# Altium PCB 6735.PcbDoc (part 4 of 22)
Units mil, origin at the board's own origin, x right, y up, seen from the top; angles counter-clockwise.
Board outline 2641.73 x 5165.35 mil, 6 copper layers (Top, Inner Layer 2, Inner Layer 3, Inner Layer 4, Inner Layer 5, Bottom), stack 35.7 mil thick; 1011 components, 790 nets, 4118 pads, 9325 vias.
Unrouted connection lines stored in the file: 4610.
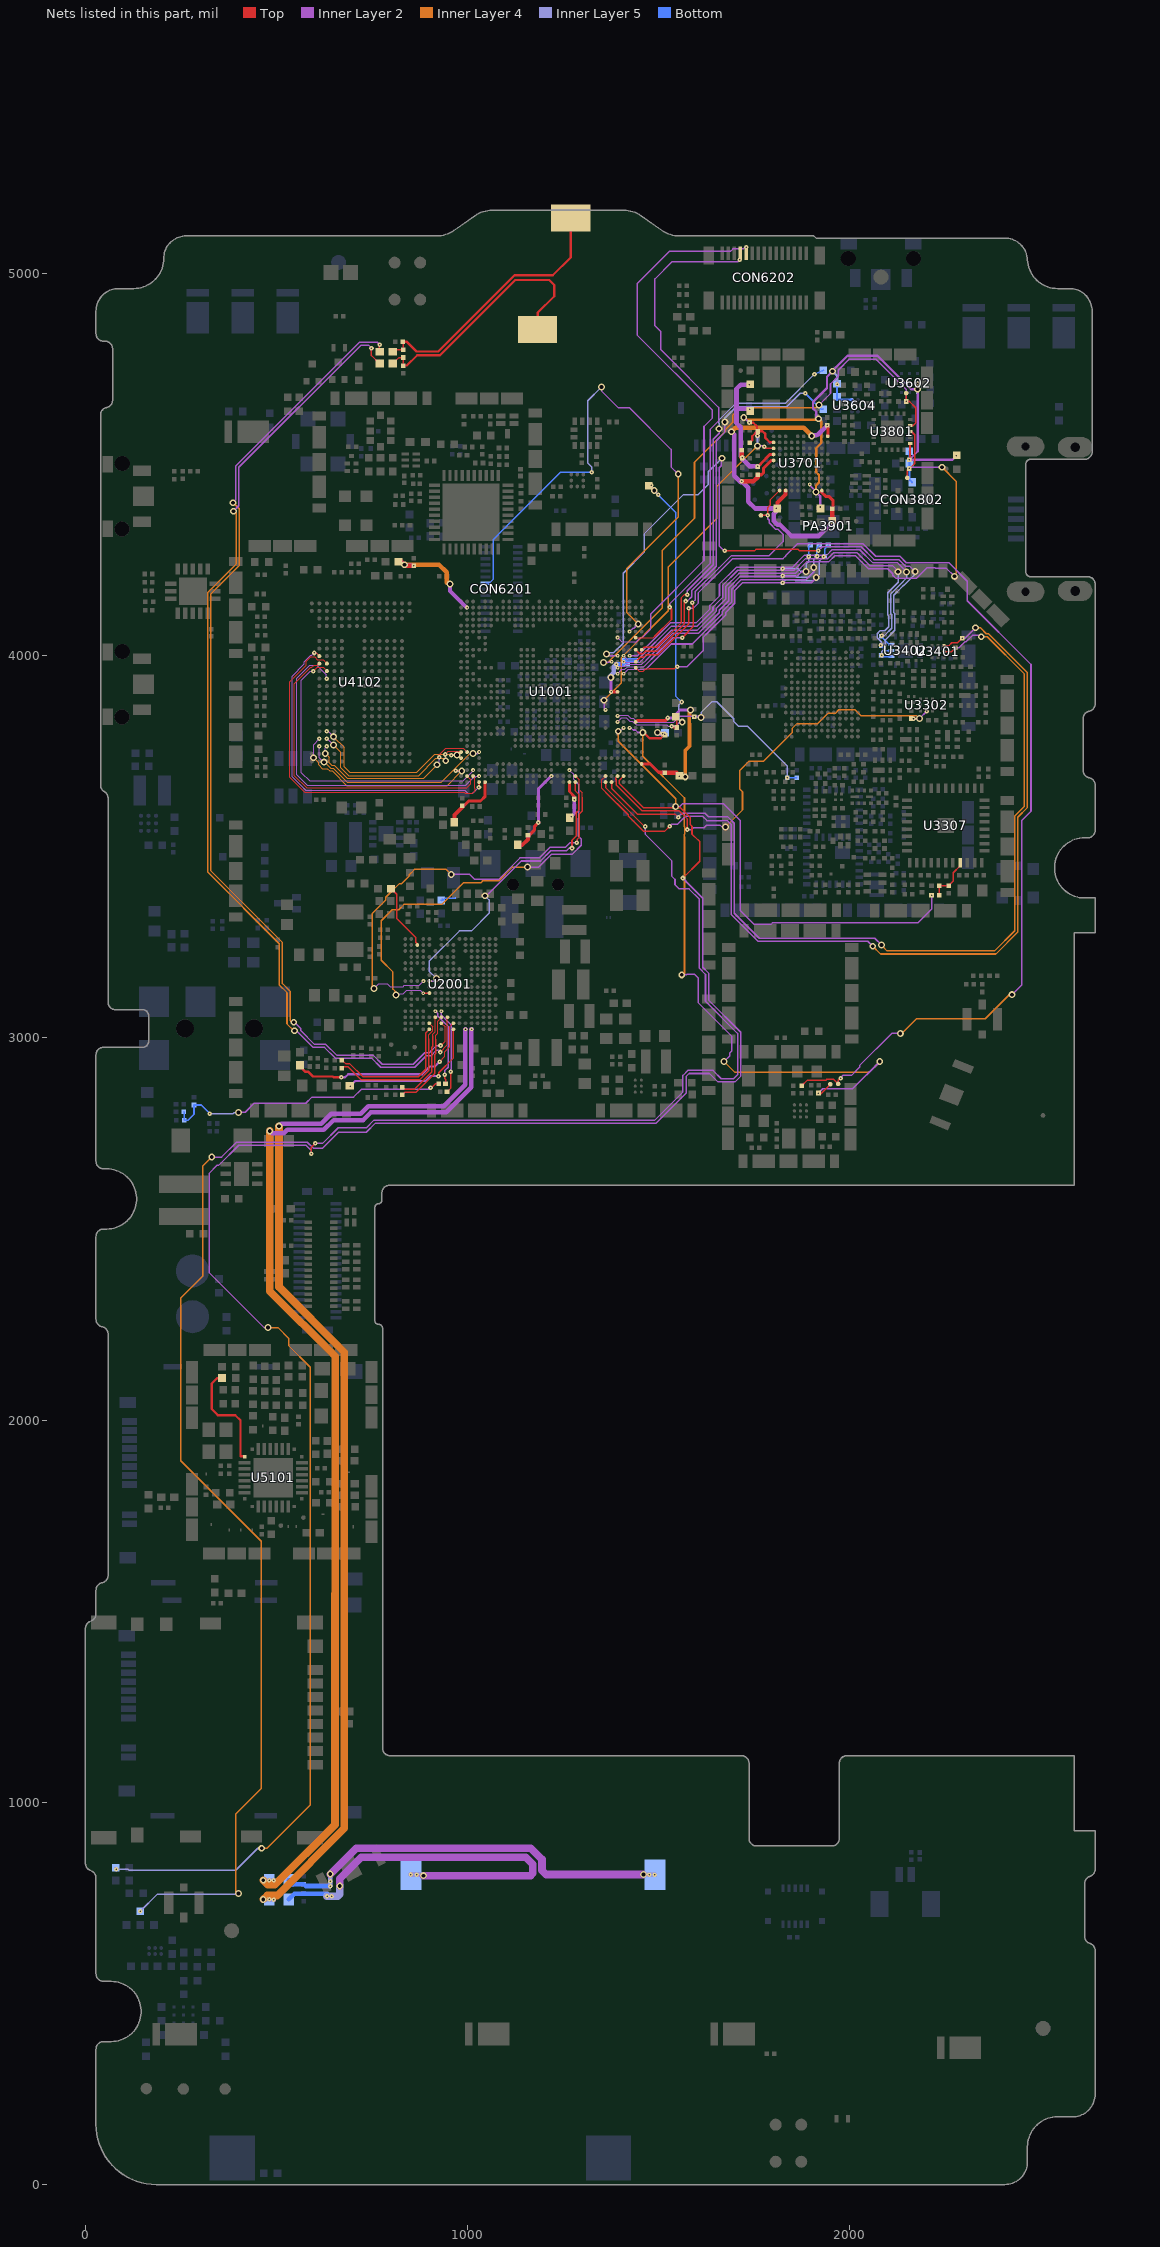
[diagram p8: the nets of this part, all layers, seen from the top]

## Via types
v1: diameter 12, hole 4, Top to Inner Layer 2, 3329 vias
v2: diameter 12, hole 4, Inner Layer 5 to Bottom, 3071 vias
v3: diameter 18, hole 10, Inner Layer 2 to Inner Layer 5, 1928 vias
v4: diameter 10, hole 4, Top to Inner Layer 2, 525 vias
v5: diameter 20, hole 12, Top to Bottom, 472 vias

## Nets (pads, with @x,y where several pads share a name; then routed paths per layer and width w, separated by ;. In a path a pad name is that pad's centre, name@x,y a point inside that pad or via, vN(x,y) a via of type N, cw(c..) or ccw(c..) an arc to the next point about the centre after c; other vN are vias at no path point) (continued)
ANT_P: C5101.2 U5101.25 | length 292.5
  Top w6: C5101.2@357.31,2110.09 357.31,2109.45 344.31,2109.45 330.41,2095.55 330.41,2029.09 346.49,2013.02 391.79,2013.02 405.38,1999.43 405.38,1905.54 415.07,1905.54 U5101.25@416.4,1904.21
APC1: R3301.1 U1001.AH10 | length 1282.5
  Top w4: R3301.1@2213.65,3373.59 v1(2213.8,3373.48)
  Inner Layer 2 w4: v3(1393.95,3802.49) 1391.03,3799.43 1393.69,3796.76 v4(1407.93,3811) ; v3(1544.25,3605.09) 1554.21,3605.09 1561.21,3612.09 1669.9,3612.09 1713.65,3568.34 1713.65,3332.62 1749.5,3296.77 1793.56,3296.77 1797.87,3301.08 2178.25,3301.08 2213.8,3336.62 v1(2213.8,3373.48)
  Inner Layer 4 w4: v3(1393.95,3802.49) 1393.95,3776.3 1544.25,3626 v3(1544.25,3605.09)
APC1_TXM: C3304.1 R3301.2 R3302.1 U3307.8 | length 121.9
  Top w4: R3301.2@2233.65,3373.59 R3302.1@2233.65,3398.59 C3304.1@2258.65,3398.59 2270.65,3410.59 2270.65,3432.09 2288.45,3449.88 U3307.8@2288.45,3458.15
APC2: R3908.1 TP3905.1 U1001.AJ10 | length 1706.8
  Top w4: R3908.1@1917.95,2855.96 v1(1916.95,2854.96) 1918.33,2853.58 1923.57,2853.58 TP3905.1@1948.95,2878.96
  Inner Layer 2 w4: v4(1423.68,3811) 1427.65,3811 1433.06,3805.59 1438.8,3805.59 1445.3,3799.09 v3(1458.3,3799.09) ; v3(1560.2,3165.08) 1572.09,3165.08 1573.92,3166.91 1592.74,3166.91 1603.6,3156.05 1603.6,3091.67 1690.31,3004.96 1690.31,2965.24 1685.42,2960.35 1685.42,2953.02 v3(1670.78,2938.38) ; v1(1916.95,2854.96) 1928.95,2866.96 2007.14,2866.96 v3(2078.04,2937.87)
  Inner Layer 4 w4: v3(1458.3,3799.09) 1458.3,3736.84 1567.31,3627.83 1567.31,3593.32 1567.15,3593.16 1567.15,3552.74 1567.56,3552.33 1567.56,3533.28 1567.15,3532.87 1567.15,3526.61 1567.31,3526.45 1567.31,3168.09 1566.13,3166.91 1560.31,3166.91 1560.1,3165.09 v3(1560.2,3165.08) ; v3(1670.78,2938.38) 1699.61,2909.56 2049.74,2909.56 v3(2078.04,2937.87)
AU_HPL: R6003.1 U2001.H15 | length 514.3
  Top w3: v1(926.9,2938.09) 940.18,2951.37 940.18,2964.03 953.31,2977.16 953.31,3028.96 U2001.H15@962.83,3038.47
  Top w4: U2001.H15@963.28,3038.47 U2001.H15@962.95,3038.47 ; U2001.H15@962.83,3038.47 963.05,3038.69 962.82,3038.92 U2001.H15@962.83,3038.47 ; U2001.H15@962.83,3038.47 962.95,3038.34 U2001.H15@962.95,3038.47 ; U2001.H15@962.83,3038.47 U2001.H15@962.95,3038.47 ; U2001.H15@962.83,3038.47 U2001.H15@962.95,3038.47
  Top w6: R6003.1@561.31,2928.09 561.31,2925.68 575.9,2911.09 583.38,2911.09 595.38,2899.09 646.55,2899.09 648.76,2896.88 v1(669.13,2896.88)
  Inner Layer 2 w6: v1(669.13,2896.88) 679.1,2896.88 687.31,2905.09 880.94,2905.09 900.94,2925.09 913.9,2925.09 v1(926.9,2938.09)
AU_HPR: R6004.1 U2001.H16 | length 389.4
  Top w4: R6004.1@690.95,2874.83 691.95,2874.83 692.49,2874.3 v1(692.49,2873.47) ; v1(923.63,2900.12) 923.93,2898.74 924.31,2898.74 924.31,2909.09 962.83,2947.6 U2001.H16@962.83,3022.72 ; U2001.H16@962.83,3022.72 963.02,3022.72 U2001.H16@962.83,3022.72
  Top w6: U2001.H16@961.95,3021.85 U2001.H16@962.83,3022.72 U2001.H16@961.95,3021.85
  Inner Layer 2 w6: v1(692.49,2873.47) 706.1,2887.09 890.84,2887.09 903.87,2900.12 v1(923.63,2900.12)
AU_HSN: R6021.1 U2001.J14 | length 2692.8
  Top w3: v1(928.31,2963.09) 946.75,2981.53 946.75,3054.22 U2001.J14@947.08,3054.22
  Top w4: v1(748.31,4804.09) 748.31,4785.13 768.95,4764.49 R6021.1@768.95,4765.49 ; R6021.1@768.95,4772.49 R6021.1@768.95,4765.49 ; R6021.1@769.35,4765.89 R6021.1@768.95,4765.49 ; R6021.1@769.95,4764.49 R6021.1@768.95,4765.49
  Inner Layer 2 w4: v3(387.31,4378.09) 401.31,4392.09 401.31,4493.18 719.96,4811.83 741.57,4811.83 748.31,4805.09 v1(748.31,4804.09) ; v3(546.95,3018.83) 552.31,3018.83 596.05,2975.09 625.61,2975.09 653.61,2947.09 748.29,2947.09 772.29,2923.09 861.53,2923.09 891.53,2953.09 903.75,2953.09 918.75,2968.09 923.31,2968.09 926.97,2964.43 v1(928.31,2963.09)
  Inner Layer 4 w4: v3(387.31,4378.09) 390.31,4378.09 394.31,4374.09 394.31,4240.08 320.31,4166.08 320.31,3433.61 507.31,3246.61 507.31,3138.71 527.31,3118.71 527.31,3036.75 546.09,3017.97 v3(546.95,3018.83)
AU_HSP: R6022.1 U2001.K15 | length 2646.6
  Top w3: v1(928.98,2980.09) 929.32,2980.09 940.75,2991.52 940.75,3029.05 U2001.K15@931.33,3038.47
  Top w4: R6022.1@769.35,4795.89 R6022.1@768.95,4795.49 ; v1(769.48,4813.59) 768.95,4813.06 R6022.1@768.95,4795.49 ; R6022.1@769.95,4795.49 767.95,4794.49 R6022.1@768.95,4795.49 ; U2001.K15@930.98,3038.82 U2001.K15@931.33,3038.47 ; U2001.K15@930.98,3038.82 931.33,3038.65 U2001.K15@931.33,3038.47 ; U2001.K15@930.98,3038.82 U2001.K15@931.33,3038.47
  Inner Layer 2 w4: v3(386.31,4400.09) 393.31,4407.09 393.31,4496.5 410.9,4514.09 594.52,4697.7 716.65,4819.83 763.24,4819.83 v1(769.48,4813.59) ; v3(544.95,3040.83) 545.99,3041.87 563.84,3024.02 563.84,3018.62 599.37,2983.09 628.93,2983.09 656.93,2955.09 752.66,2955.09 776.66,2931.09 857.85,2931.09 887.85,2961.09 899.3,2961.09 918.3,2980.09 v1(928.98,2980.09)
  Inner Layer 4 w4: v3(386.31,4400.09) 386.53,4400.31 402.31,4384.53 402.31,4235.95 328.31,4161.95 328.31,3436.93 515.31,3249.93 515.31,3142.05 535.31,3122.05 535.31,3046.09 540.57,3040.83 v3(544.95,3040.83)
AU_OUT0_N_OUT: C6025.2 C6032.1 R6021.2 REC6001.2 | length 682.6
  Top w4: R6021.2@803.95,4764.49 804.95,4764.49 820.55,4780.09 C6025.2@831.31,4780.09 C6032.1@831.31,4759.09
  Top w6: C6032.1@831.31,4759.09 840.91,4759.09 867.91,4786.09 927.31,4786.09 1124.31,4983.09 1213.31,4983.09 1226.31,4970.09 1226.31,4940.63 1182.99,4897.31 REC6001.2@1183,4853.42
AU_OUT0_P_OUT: C6025.1 C6031.1 R6022.2 REC6001.1 | length 705
  Top w4: R6022.2@803.95,4795.49 804.95,4795.49 809.55,4800.09 C6025.1@831.31,4800.09 831.46,4800.24 831.46,4819.94 831.31,4820.09 C6031.1@830.31,4821.09
  Top w6: C6031.1@830.31,4821.09 841.2,4821.09 866.2,4796.09 923.17,4796.09 1122.4,4995.32 1222.75,4995.32 1269.61,5042.18 REC6001.1@1269.61,5144.76
AU_SPK1N: R6019.2 U2001.E16 | length 2918.5
  Inner Layer 2 w12: v3(482.31,2756.35) 488.57,2750.09 518.47,2750.09 527.91,2759.53 623.8,2759.53 649.37,2785.09 726.94,2785.09 746.94,2805.09 943.75,2805.09 984.75,2846.09 984.86,2846.09 1009.52,2870.75 1009.52,3022.17 v4(1010.07,3022.72)
  Inner Layer 4 w20: v3(465.31,796.09) 477.31,784.09 495.37,784.09 652.95,941.67 652.95,1545.47 653.31,1545.83 653.31,2166.76 482.31,2337.76 v3(482.31,2756.35)
  Inner Layer 5 w12: v3(465.31,796.09) v2@478.67,796.09 ; v2(480.82,795.85) v2@478.67,796.08 ; v2(492.95,795.78) 492.64,796.09 v2@478.67,796.09
  Bottom w4: v2(480.82,795.85) R6019.2@480.72,796.09 490.31,796.09 491.31,795.09 491.36,795.11 v2(492.95,795.78)
AU_SPK1P: R6020.2 U2001.F16 | length 2926.3
  Inner Layer 2 w12: v3(506.31,2769.09) 512.78,2775.56 617.16,2775.56 642.7,2801.09 719.86,2801.09 739.86,2821.09 937.12,2821.09 978.12,2862.09 978.23,2862.09 993.42,2877.28 993.42,3021.81 v4(994.32,3022.72)
  Inner Layer 4 w20: v3(465.31,746.09) 475.31,756.09 501.31,756.09 676.95,931.73 676.95,1524.17 677.31,1524.54 677.31,2177.42 506.31,2348.42 v3(506.31,2769.09)
  Inner Layer 5 w12: v3(465.31,746.09) v2(480.72,746.09) 480.72,745.87 492.97,745.87 v2(492.97,745.65)
  Bottom w4: v2(492.97,745.65) 491.31,746.09 v2(480.72,746.09) ; v2(480.72,746.09) 476.72,750.09 v2(480.72,746.09)
AU_SPK_N: C6024.1 R6019.1 SPK6001.1 | length 1125.5
  Inner Layer 2 w20: v3(640.31,812.09) 708.31,880.09 1165.31,880.09 1194.31,851.09 1194.31,822.09 1205.31,811.09 v3(1459.65,811.09)
  Inner Layer 5 w4: v2(1475.21,810.82) 1475.21,810.71 v2@1489.85,810.71
  Inner Layer 5 w12: v2(639.96,780.86) 640.14,780.86 640.14,812.09 v3(640.31,812.09) ; v3(1459.65,811.09) 1459.65,810.84 1489.85,810.84 1489.85,810.71 v2(1489.85,810.59)
  Bottom w4: v2(639.96,780.86) 639.73,781.09 637.3,783.52 639.59,785.81 638.31,787.09 639.96,787.09 640.31,787.09 640.56,790.95 639.96,791.1 639.58,791.19 639.96,792.75 v2(640.22,793.82) ; SPK6001.1@1489.85,810.59 1489.85,815.55 v2(1489.85,810.59)
  Bottom w12: R6019.1@531.9,796.09 541.91,786.09 C6024.1@571.31,786.09 576.31,781.09 v2@639.73,781.09 ; v2(639.96,780.86) 639.96,787.09 639.96,791.1 639.96,792.75 639.96,793.56 v2(640.22,793.82)
AU_SPK_P: C6023.2 R6020.1 SPK6001.2 | length 1134.1
  Inner Layer 2 w20: v3(665.31,781.09) 665.31,800.09 721.31,856.09 1152.31,856.09 1170.31,838.09 1170.31,814.09 1164.31,808.09 v3(884.31,808.09)
  Inner Layer 5 w4: v2(851.31,811.09) 851.31,810.94 866.4,810.94 v2(866.4,810.78)
  Inner Layer 5 w12: v2(851.31,811.09) 884.31,811.09 v3(884.31,808.09)
  Inner Layer 5 w20: v2(632.06,754.32) 659.84,754.32 659.9,754.26 ; v2(644.19,754.26) 659.9,754.26 ; v3(665.31,781.09) 665.31,759.67 659.9,754.26
  Bottom w4: v2(632.06,754.32) 632.81,754.76 637.01,754.98 638.91,755.09 638.11,754.29 v2@637.91,754.09 ; v2(851.31,811.09) 851.55,811.09 SPK6001.2@852.06,810.59
  Bottom w12: R6020.1@531.9,746.09 546.91,761.09 C6023.2@571.31,761.09 630.9,761.09 637.01,754.98 v2@637.71,754.29 ; v2(632.06,754.32) v2@637.71,754.29 ; v2@637.71,754.29 637.91,754.09 v2(644.19,754.26) 638.11,754.29 v2@637.71,754.29
AU_VIN0_N: R6026.2 U2001.M15 | length 390.1
  Top w3: 898.31,2998.09 898.31,3007.8 909.26,3018.74 909.26,3029.05 U2001.M15@899.83,3038.47
  Top w4: R6026.2@670.31,2921.09 R6026.2@671.31,2921.09 ; R6026.2@674.31,2918.09 R6026.2@671.31,2921.09 ; 898.31,2998.09 898.31,2914.4 874,2890.09 721.75,2890.09 687.75,2924.09 674.31,2924.09 R6026.2@671.31,2921.09
AU_VIN0_P: R6025.2 U2001.M16 | length 355.3
  Top w4: R6025.2@670.31,2942.09 671.31,2942.09 681.31,2932.09 691.89,2932.09 725.89,2898.09 870.69,2898.09 890.31,2917.71 890.31,3013.2 U2001.M16@899.83,3022.72
AU_VIN1_N: R6027.1 U2001.L13 | length 209
  Top w4: v1(940.31,2904.13) 940.31,2893.63 942.95,2890.99 942.95,2880.49 R6027.1@941.95,2880.49
  Inner Layer 2 w4: v4(915.58,3069.96) 922.31,3063.23 922.31,3056.58 948.98,3029.91 948.98,2923.09 940.31,2914.42 v1(940.31,2904.13)
AU_VIN1_N1: C6019.1 C6020.2 R6027.2 R6029.1 | length 763.4
  Top w4: v1(902.86,2869.1) 904.98,2869.11 916.35,2880.49 R6027.2@923.95,2880.49
  Inner Layer 2 w4: v3(400.56,2804.69) 400.56,2805.41 417.89,2805.41 441.31,2828.83 576.42,2828.83 592.68,2845.09 701.32,2845.09 721.32,2865.09 898.85,2865.09 v1(902.86,2869.1)
  Inner Layer 5 w4: v2(325.15,2802.01) 386.87,2802.01 389.56,2804.69 v3(400.56,2804.69)
  Bottom w4: v2(325.15,2802.01) 302.67,2824.49 R6029.1@283.95,2824.49 283.95,2800.23 268.22,2784.49 C6020.2@257.95,2784.49 C6019.1@257.95,2805.49 ; C6019.1@257.95,2805.49 C6019.1@256.95,2806.49 257.95,2806.49 C6019.1@257.95,2805.49
AU_VIN1_P: R6028.1 U2001.K13 | length 231.1
  Top w4: R6028.1@943.6,2859.05 945.89,2859.7 946.01,2859.73 R6028.1@946.95,2859.49 ; R6028.1@945.95,2859.49 R6028.1@946.95,2859.49 ; v1(955.41,2911.66) 955.41,2867.94 R6028.1@946.95,2859.49
  Inner Layer 2 w4: v4(931.33,3069.96) 931.33,3059.54 957.31,3033.56 957.31,2911.66 v1(955.41,2911.66)
AU_VIN2_N: R6024.2 U2001.L14 | length 247
  Top w3: 908.31,3005.09 908.31,3009.09 915.31,3016.09 915.31,3053.95 U2001.L14@915.58,3054.22
  Top w4: R6024.2@828.31,2871.09 829.31,2871.09 834.32,2866.09 835.31,2866.09 861.32,2866.09 906.31,2911.09 906.31,2975.56 908.31,2977.56 908.31,3005.09 ; U2001.L14@915.58,3053.83 915.95,3053.83 U2001.L14@915.58,3054.22 U2001.L14@915.58,3053.83
AU_VIN2_P: R6023.2 U2001.K14 | length 264.4
  Top w3: 916.31,2996.09 916.31,3007.61 921.31,3012.61 921.31,3044.2 930.96,3053.85 U2001.K14@931.33,3054.22
  Top w4: R6023.2@828.31,2851.09 829.31,2851.09 836.31,2858.09 864.63,2858.09 914.31,2907.77 914.31,2957.36 916.31,2959.36 916.31,2996.09 ; U2001.K14@930.96,3053.85 931.23,3054.28 U2001.K14@931.33,3054.45 ; U2001.K14@931.33,3054.45 U2001.K14@931.33,3054.22 931.54,3054.43 U2001.K14@931.35,3054.45
AUD_CLK_MOSI: U1001.Y1 U2001.M8 | length 797.6
  Top w4: v1(1272.95,3496.83) 1272.95,3517.04 1283.95,3528.04 1283.95,3589.09 1290.95,3596.09 1290.95,3637.12 1281.94,3646.13 U1001.Y1@1281.94,3669.27
  Inner Layer 2 w4: v4(899.83,3148.7) 911.92,3148.7 v3(918.31,3155.09) ; v3(1044.95,3371.83) 1049.21,3371.83 1140.22,3462.84 1190.62,3462.84 1217.46,3489.68 1258.28,3489.68 1264.95,3496.35 1272.95,3496.35 v1(1272.95,3496.83)
  Inner Layer 5 w4: v3(918.31,3155.09) 898.93,3174.47 898.93,3200.37 978.39,3279.83 1009.92,3279.83 1055.95,3325.86 1055.95,3360.83 v3(1044.95,3371.83)
AUD_DAT_MISO_1: U1001.W3 U2001.M10 | length 1125.2
  Top w4: v4(883.95,3116.83) 883.95,3117.02 899.83,3117.02 U2001.M10@899.83,3117.21
  Inner Layer 2 w3: v3(812.86,3112.06) 812.86,3116.09 831.37,3116.09 840.37,3125.09 875.69,3125.09 v4(883.95,3116.83) ; v4(1266.2,3700.77) 1276.95,3690.01 1276.95,3677.09
  Inner Layer 2 w4: v3(1156.95,3446.83) 1185.94,3446.83 1219.94,3480.83 1273.92,3480.83 1296.95,3503.86 1296.95,3520.66 1288.95,3528.66 1288.95,3574.16 1290.87,3576.08 1290.87,3663.17 1276.95,3677.09
  Inner Layer 4 w4: v3(812.86,3112.06) 812.86,3119.15 804.31,3127.7 804.31,3172.54 773.95,3202.9 773.95,3306.67 802.74,3335.46 819.67,3335.46 833.3,3349.09 932.07,3349.09 989.07,3406.09 1034.71,3406.09 1039.71,3411.09 1081.23,3411.09 1116.97,3446.83 v3(1156.95,3446.83)
AUD_DAT_MOSI_1: U1001.Y2 U2001.N8 | length 1168.8
  Top w3: U1001.Y2@1281.94,3685.02 1286.32,3680.64 ; 1286.32,3680.6 1290.69,3676.23 1291.53,3675.39 1291.53,3649.06 1299.31,3641.28 1299.31,3629.09
  Top w4: v1(1284.95,3510.83) 1286.31,3510.83 1286.31,3518.96 1292.43,3525.07 1292.43,3586.25 1299.31,3593.14 1299.31,3629.09
  Inner Layer 2 w3: v3(755.31,3129.09) 767.31,3141.09 790.14,3141.09 797.14,3134.09 830.88,3134.09 834.69,3137.9 873.28,3137.9 v4(884.09,3148.7)
  Inner Layer 2 w4: v3(956.95,3427.83) 1005.35,3427.83 1018.41,3414.77 1080.32,3414.77 1136.59,3471.03 1187.49,3471.03 1214.84,3498.38 1255.56,3498.38 1268.01,3510.83 v1(1284.95,3510.83)
  Inner Layer 4 w4: v3(755.31,3129.09) 749.95,3134.45 749.95,3325.12 785.95,3361.12 785.95,3368.25 821.53,3403.83 827.27,3403.83 846.95,3423.51 846.95,3426.98 860.8,3440.83 943.95,3440.83 v3(956.95,3427.83)
AUX_IN0_NTC: C1106.1 NTC6301.1 R6314.2 U1001.AG11 | length 935.4
  Top w4: NTC6301.1@1469.95,4440.49 NTC6301.1@1472.76,4443.3 ; v1(1534.31,3815.09) 1537.31,3812.09 C1106.1@1547.31,3812.09 1547.31,3837.09 R6314.2@1544.31,3840.09 ; NTC6301.1@1472.76,4443.3 NTC6301.1@1477.31,4438.75 ; NTC6301.1@1472.76,4443.3 NTC6301.1@1473.79,4444.33 ; NTC6301.1@1472.76,4443.3 1472.76,4444.49 NTC6301.1@1473.79,4444.49 ; NTC6301.1@1473.79,4444.33 NTC6301.1@1473.79,4444.49 ; NTC6301.1@1473.79,4444.33 NTC6301.1@1473.95,4444.49 ; NTC6301.1@1473.79,4444.49 NTC6301.1@1473.95,4444.49 ; NTC6301.1@1473.95,4444.49 1477.31,4444.49 NTC6301.1@1477.31,4438.75 ; NTC6301.1@1477.31,4438.75 1478.5,4437.56 1479.61,4443.42 v1(1480.03,4445.62) 1478.82,4442.57 NTC6301.1@1477.31,4438.75 ; v4(1392.18,3826.75) 1392.3,3826.75 1392.3,3826.62 v4(1392.18,3826.75)
  Inner Layer 2 w3: v4(1392.18,3826.75) 1403.26,3837.83 1414.95,3837.83 1423.95,3828.83 1430.79,3828.83 1440.53,3819.09 1521.06,3819.09 1525.06,3815.09 v1(1534.31,3815.09)
  Inner Layer 2 w4: v1(1480.03,4445.62) 1478.77,4444.36 1489.53,4433.59 v3(1488.28,4432.34) ; v1(1534.31,3815.09) 1543.31,3815.09 1555.08,3826.86 1560.54,3826.86 v3(1561.31,3826.09)
  Inner Layer 5 w4: v3(1488.28,4432.34) 1487.96,4432.02 1498.94,4421.04 v2(1498.62,4420.72) ; v2(1559.95,3878.83) 1552.31,3871.19 1552.31,3835.09 v3(1561.31,3826.09)
  Bottom w4: v2(1498.62,4420.72) 1543.95,4375.38 1543.95,3894.83 v2(1559.95,3878.83)
AUX_IN1_NTC: C1105.1 NTC6302.1 R3232.2 U1001.AG12 | length 631.3
  Top w3: v4(1392.18,3842.5) 1392.3,3842.37 v4(1392.18,3842.5)
  Top w4: v1(1593.34,3839.74) C1105.1@1593.31,3840.09
  Inner Layer 2 w3: v4(1392.18,3842.5) 1392.18,3843.83 1393.18,3844.83 1418.94,3844.83 1426.94,3836.83 1430.29,3836.83 1431.31,3835.82 1433.72,3835.82 1443.45,3826.09 1538.88,3826.09 1554.88,3842.09
  Inner Layer 2 w4: 1554.88,3842.09 1595.3,3842.09 v1@1596.49,3840.91 ; v3(1610.65,3838.33) 1608.07,3840.91 v1@1596.49,3840.91 ; v1@1593.69,3840.09 v1(1593.34,3839.74) v1@1597.3,3840.09 ; v1@1593.69,3840.09 v1@1597.3,3840.09 ; v1@1593.69,3840.09 1593.31,3840.09 1592.5,3840.91 v1@1596.49,3840.91 ; v1@1596.49,3840.91 v1@1597.3,3840.09
  Inner Layer 5 w4: v3(1610.65,3838.33) 1610.65,3851.23 1639.13,3879.71 1651.56,3879.71 1696.3,3834.97 1696.3,3827.97 1708.93,3815.34 1732.29,3815.34 1827.5,3720.13 1827.5,3720.04 1835.65,3711.88 v2(1835.65,3680.59)
  Bottom w4: v2(1835.65,3680.59) NTC6302.1@1860.65,3680.59
AVDD18_ARMPLL: C10083.1 R1009.1 U1001.AG16 | length 162.3
  Top w8: v4(1375.3,3905.09) 1375.3,3905.29 1392.18,3905.29 U1001.AG16@1392.18,3905.49
  Inner Layer 2 w8: v3(1374.52,3943.04) 1375.33,3942.23 v3@1375.33,3937.92 ; v4(1375.3,3905.09) v3@1375.3,3937.89
  Inner Layer 5 w12: v3@1375.21,3942.36 v3(1374.52,3943.04) 1371.89,3945.67 1382.31,3956.09 1382.31,3971.66 v2(1388.53,3977.87)
  Bottom w12: v2(1388.53,3977.87) 1404.1,3977.87 1411.27,3985.05 1411.27,3983 R1009.1@1414.31,3983 1414.31,3988.09 C10083.1@1441.31,3988.09
AVDD18_MD: C10078.1 R1004.1 U1001.AK11 U1001.AL4 | length 470.4
  Top w8: U1001.AK11@1439.43,3826.75 1442.76,3830.09 1517.31,3830.09 1523.31,3836.09 v1(1523.31,3837.09) ; U1001.AL4@1455.17,3716.51 1477.88,3716.51 1499.3,3695.09 1515.3,3695.09 C10078.1@1515.3,3694.09
  Top w12: C10078.1@1515.3,3694.09 1546.3,3694.09 1552.56,3687.82 1553.31,3686.09 R1004.1@1554.31,3686.09
  Inner Layer 2 w8: v1(1523.31,3837.09) 1534.62,3837.09 1555.62,3858.09 v3(1583.31,3858.09)
  Inner Layer 2 w12: v1(1553.31,3684.09) 1569.31,3684.09 v3(1569.31,3683.09)
  Inner Layer 4 w10: v3(1569.31,3683.09) 1569.31,3752.09 1580.31,3763.09 1580.31,3821.6 1579.5,3822.41 1579.5,3843.95 1580.31,3844.76 1580.31,3858.09 v3(1583.31,3858.09)
AVDD18_MEMPLL: C10098.1 R1018.1 U1001.E1 | length 161.1
  Top w8: C10098.1@986.31,3607.09 988.14,3607.09 988.14,3605.26 1002.88,3620 1033.46,3620 1045.72,3632.26 U1001.E1@1045.72,3669.27
  Top w10: R1018.1@965.31,3564.09 965.31,3583.19 986.31,3604.19 C10098.1@986.31,3607.09
AVDD18_USB: C10100.1 R1029.1 U1001.W1 | length 98.9
  Top w8: U1001.W1@1266.2,3669.27 1266.19,3644.59 1278.95,3631.83 C10100.1@1278.95,3625.49 v1(1278.87,3623.6)
  Inner Layer 2 w10: v1(1271.45,3578.84) 1278.95,3586.33 v1(1278.87,3623.6) v1(1278.87,3623.6)
AVDD18_WBG: C10099.1 R1031.1 U1001.B30 | length 317
  Top w12: R1031.1@818.95,4245.83 819.95,4245.83 819.95,4249.07 823.19,4249.07 837.44,4234.83 v1(858.95,4234.83)
  Inner Layer 2 w10: v3(953.95,4187.83) 953.95,4169.22 997.23,4125.94 997.23,4126.16 v4@995.3,4128.09
  Inner Layer 2 w12: v3@832.45,4237.99 v3(834.45,4237.99) 834.45,4234.83 v1(858.95,4234.83)
  Inner Layer 4 w12: v3(834.45,4237.99) 924.95,4237.99 944.95,4217.99 944.95,4190.99 949.95,4189.83 v3(953.95,4187.83)
  other v4: 998.48,4125.96
AVDD28_DAC: C10090.1 R1035.1 U1001.AL9 | length 122.9
  Top w4: C10090.1@1515.3,3792.09 v1(1515.3,3795.09) C10090.1@1516.3,3792.09 C10090.1@1515.3,3792.09
  Top w6: U1001.AL9@1455.17,3795.25 1464.75,3795.25 1475.91,3784.09 1505.3,3784.09 1514.8,3793.59 1514.8,3792.09 C10090.1@1515.3,3792.09 ; v1(1515.3,3795.09) C10090.1@1516.3,3795.09
  Inner Layer 2 w10: v3(1496.3,3799.09) 1500.3,3795.09 v1(1515.3,3795.09)
  Inner Layer 5 w6: v3(1496.3,3799.09) 1507.44,3799.09 v2(1510.92,3795.61)
  Bottom w4: v2(1510.92,3795.61) 1515.31,3795.61 1515.31,3798.09 R1035.1@1516.31,3798.09
AVDD33_USB_P0: C10095.1 R1030.1 U1001.T2 | length 230.9
  Top w4: v4(1218.95,3685.02) 1218.95,3685.49 1219.42,3685.49 v4(1218.95,3685.02)
  Top w8: C10095.1@1157.95,3530.49 1159.61,3530.49 1159.61,3528.83 1174.31,3543.54 1174.31,3552.85 v1(1184.95,3563.49)
  Top w10: R1030.1@1130.95,3505.49 1130.95,3504.49 1142.95,3504.49 1157.95,3519.49 C10095.1@1157.95,3530.49
  Inner Layer 2 w8: v1(1184.95,3563.49) 1184.95,3651.01 v4(1218.95,3685.02)
BAT_ON: R2105.2 U2001.P2 | length 181.5
  Top w4: R2105.2@799.31,3390.09 800.31,3390.09 814.31,3376.09 814.31,3312.64 842.46,3284.49 ; 839.49,3287.49 842.49,3284.49 863.95,3263.02 863.95,3250.38 869.74,3244.59 U2001.P2@868.34,3243.19
BATSNS: R2043.1 R2140.1 | length 44.3
  Bottom w4: R2043.1@930.95,3359.49 R2043.1@930.95,3360.49 ; R2043.1@933.95,3363.49 R2043.1@930.95,3360.49 ; R2140.1@967.95,3365.49 940.95,3365.49 935.95,3360.49 R2043.1@930.95,3360.49
BPI_BUS0: R3613.1 U1001.AH2 | length 4903.5
  Top w4: U1001.AH2@1407.93,3685.02 1397.01,3674.1 1397.01,3664.75 1459.86,3601.89 1556.95,3601.89 1582.95,3575.88 1582.95,3557.76 1586.95,3553.76 1586.95,3532.91 1593.98,3525.88 1594.61,3525.88 1606.95,3513.54 1606.95,3461.98 v1(1563.31,3418.34)
  Inner Layer 2 w4: v3(330.31,2688.09) 356.2,2688.09 395.2,2727.09 580.52,2727.09 596.52,2711.09 620.15,2711.09 662.15,2753.09 734.55,2753.09 758.55,2777.09 1493.18,2777.09 1571.31,2855.22 1571.31,2898.86 1579.35,2906.9 1632.67,2906.9 1654.83,2884.74 1699.4,2884.74 1715.06,2900.4 1715.06,3013.86 1714.31,3014.61 1714.31,3015.08 1630.28,3099.11 1630.28,3169.58 1614.79,3185.07 1614.79,3365.65 1570.55,3409.89 1570.55,3411.1 v1(1563.31,3418.34)
  Inner Layer 4 w4: v3(330.31,2688.09) 306.95,2664.72 306.95,2377.09 249.31,2319.45 249.31,1893.88 459.95,1683.24 459.95,1036.36 393.31,969.72 393.31,761.09 v3(400.48,761.09)
  Inner Layer 5 w4: v2(143.31,715.09) 188.31,760.09 400.48,760.09 v3(400.48,761.09)
BPI_BUS1: R3617.2 U1001.AE1 | length 4857.6
  Top w4: v1(590.55,2697.25) 590.55,2713.38 v1(601.12,2723.95) ; U1001.AE1@1360.69,3669.27 1360.69,3655.4 1463,3553.09 v1(1464.31,3553.09)
  Inner Layer 2 w4: v3(477.31,2242.09) 467.31,2242.09 323.31,2386.09 323.31,2645.49 345.01,2667.18 349.06,2667.18 400.97,2719.09 576.71,2719.09 590.55,2705.25 v1(590.55,2697.25) ; v1(601.12,2723.95) 619.99,2723.95 661.13,2765.09 735.23,2765.09 755.23,2785.09 1489.86,2785.09 1563.13,2858.36 1563.13,2902 1576.03,2914.9 1641.83,2914.9 1663.67,2893.06 1695.55,2893.06 1706.31,2903.82 1706.31,3011.68 1622.27,3095.72 1622.27,3166.12 1605.63,3182.76 1605.63,3363.12 1579.09,3389.66 1553.34,3389.66 1542.43,3400.57 1542.43,3414.44 1534.31,3422.56 1534.31,3463.17 1464.31,3533.17 v1(1464.31,3553.09)
  Inner Layer 4 w4: v3(461.07,879.76) 474.8,879.76 588.31,993.28 588.31,2138.47 531.31,2195.47 531.31,2214.3 503.53,2242.09 v3(477.31,2242.09)
  Inner Layer 5 w4: v2(80.95,824.49) 111.84,824.49 114.24,822.09 393.31,822.09 450.99,879.76 v3(461.07,879.76)
  Bottom w4: R3617.2@78.95,828.49 80.95,826.49 v2(80.95,824.49)
BPI_BUS2: C3313.1 U1001.AG2 U3302.8 | length 1152.6
  Top w4: U1001.AG2@1392.18,3685.02 1387.29,3680.12 1387.29,3677 1388.18,3676.1 1388.18,3662.26 1456.55,3593.89 1553.63,3593.89 1574.95,3572.57 v1(1574.95,3545.23)
  Top w5: C3313.1@2160.65,3835.59 2160.65,3835.18 v1(2166.46,3835.18)
  Inner Layer 2 w4: v1(1574.95,3545.23) 1586.1,3545.23 1590.75,3549.88 1618.03,3549.88 1624.06,3555.91 1661.32,3555.91 1665.14,3552.1 v3(1674.65,3552.1) ; v1(2166.46,3835.18) 2166.46,3835.28 2182.12,3835.28 v3(2182.12,3835.38) 2181.89,3835.61 2200.88,3854.61 v1(2200.65,3854.84)
  Inner Layer 4 w4: v3(1674.65,3552.1) 1719.08,3596.52 1719.08,3644.05 1712.3,3650.82 1712.3,3700.05 1736.27,3724.03 1774.19,3724.03 1848.65,3798.49 1848.65,3809.8 1860.44,3821.59 1914.48,3821.59 1942.43,3849.54 1962.02,3849.54 1971.07,3858.59 2013.56,3858.59 2029.24,3842.91 2174.59,3842.91 v3(2182.12,3835.38)
BPI_BUS3: C3456.2 U1001.AE2 U3401.1 | length 2475.7
  Top w3: U1001.AE2@1360.69,3685.02 1351.26,3675.6 1351.26,3652.59 1360.88,3642.97
  Top w4: 1360.88,3642.97 1420.16,3583.69 1420.16,3580.27 1459.34,3541.09 1515.98,3541.09 v1(1528.79,3553.91) ; U3401.1@2246.4,4026.34 2259.4,4026.34 2266.65,4033.59 2281.65,4033.59 C3456.2@2293.65,4045.59 v1(2293.65,4045.83)
  Inner Layer 2 w4: v1(1528.79,3553.91) 1533.76,3558.87 1548.66,3558.87 1569.67,3579.88 1614.63,3579.88 1625.86,3568.65 1679.31,3568.65 1689.65,3558.31 1689.65,3322.68 1759.56,3252.77 2047,3252.77 v3(2059.93,3239.84) ; v1(2293.65,4045.83) 2293.65,4045.59 2301.04,4045.59 v3(2328.58,4073.13)
  Inner Layer 4 w4: v3(2059.93,3239.84) 2080.23,3219.54 2381.97,3219.54 2439.43,3277 2439.43,3369.74 ; v3(2328.58,4073.13) 2341.43,4073.13 2357.03,4057.52 2362.75,4057.52 2464.65,3955.62 2464.65,3602.74 2439.4,3577.49 2439.4,3425.56 2439.41,3369.76
BPI_BUS4: C3457.2 U1001.AF1 U3401.8 | length 2369.7
  Top w4: U1001.AF1@1376.43,3669.27 1376.43,3652.94 1444.71,3584.66 1543.67,3584.66 v1(1550.55,3577.78) ; U3401.8@2246.4,4010.59 2265.65,4010.59 v1(2275.65,4020.59)
  Inner Layer 2 w4: v1(1550.55,3577.78) 1560.65,3587.88 1620.8,3587.88 1630.48,3578.2 1681.08,3578.2 1697.65,3561.62 1697.65,3325.99 1762.88,3260.77 2065.24,3260.77 v3(2083.11,3242.9) ; v1(2275.65,4020.59) 2285.53,4020.59 2302.03,4037.09 2304.75,4037.09 2320.72,4053.06 2341.13,4053.06 2344.24,4049.95 v3(2343.82,4049.52)
  Inner Layer 4 w4: v3(2083.11,3242.9) 2083.14,3240.77 2085.72,3239 2097.18,3227.54 2378.66,3227.54 2431.4,3280.28 2431.4,3580.8 2456.65,3606.05 2456.65,3952.3 2359.43,4049.52 v3(2343.82,4049.52)
BPI_BUS5: R3616.1 U1001.AL23 | length 1036.3
  Top w4: U1001.AL23@1455.17,4015.73 1461.53,4022.09 1494.71,4022.09 1558.31,4085.69 1558.31,4151.09 1566.31,4159.09 v1(1574.31,4159.09)
  Inner Layer 2 w4: v1(1574.31,4159.09) 1574.31,4169.86 1642.31,4237.86 1642.31,4566.58 1657.95,4582.22 v3(1657.95,4593.83)
  Inner Layer 5 w4: v3(1657.95,4593.83) 1657.95,4607.45 1657.31,4608.09 1657.31,4616.93 1700.47,4660.09 1830.62,4660.09 v2(1907.37,4736.84)
  Bottom w4: v2(1907.37,4736.84) 1930.46,4746.73 1931.3,4747.09 R3616.1@1930.3,4747.09
BPI_BUS6: R3619.2 U1001.AK23 | length 1051.8
  Top w4: U1001.AK23@1439.43,4015.73 1450.06,4005.09 1459.07,4005.09 1465.05,4011.06 1495,4011.06 1566.31,4082.37 1566.31,4138.37 v1(1570.95,4143.01)
  Inner Layer 2 w4: v1(1570.95,4143.01) 1575.2,4143.01 1586.57,4154.37 1586.57,4170.41 1650.31,4234.15 1650.31,4562.67 1672.95,4585.31 1672.95,4597.87 1672.83,4597.99 v3(1672.83,4611.24)
  Inner Layer 5 w4: v3(1672.83,4611.24) 1672.83,4621.14 1702.78,4651.09 1834.64,4651.09 1870.38,4686.83 v2(1882.95,4686.83)
  Bottom w4: v2(1882.95,4686.83) 1924.69,4645.09 R3619.2@1930.3,4645.09 R3619.2@1930.3,4646.09
BPI_BUS7: C3447.2 U1001.AJ22 U3402.7 | length 1125.6
  Top w4: v4(1423.68,3999.98) 1423.67,4000.09 1423.79,4000.09 v4(1423.68,3999.98)
  Inner Layer 2 w4: v4(1423.68,3999.98) 1444.28,3999.98 1530.14,4085.85 1597.39,4085.85 1633.81,4122.27 1633.81,4131.45 1658.86,4156.51 1658.86,4187.27 1703.3,4231.71 1849.74,4231.71 1880.25,4262.22 1938.63,4262.22 1953.56,4277.15 2025.81,4277.15 2059.31,4243.65 2123.76,4243.65 2148.53,4218.87 v3(2148.31,4218.65)
  Inner Layer 5 w4: v2(2083.81,4052.65) 2090.34,4052.65 2109.56,4071.87 2109.56,4107.03 2106.81,4109.78 2106.81,4111.45 2106.81,4161.56 2131.67,4186.41 2148.31,4203.05 v3(2148.31,4218.65)
  Bottom w4: C3447.2@2081.65,4051.09 C3447.2@2081.65,4051.09 ; v2(2083.81,4052.65) 2083.49,4052.76 2083.45,4052.8 C3447.2@2081.65,4051.09 ; U3402.7@2108.31,4028.9 2103.84,4028.9 C3447.2@2081.65,4051.09
BPI_BUS8: C3439.2 U1001.AH22 U3402.6 | length 1148.4
  Top w4: v4(1407.93,3999.98) 1407.93,4000.09 1408.04,4000.09 v4(1407.93,3999.98)
  Inner Layer 2 w3: v4(1407.93,3999.98) 1418.43,3989.47 1445.27,3989.47 1452.93,3997.13
  Inner Layer 2 w4: 1452.93,3997.13 1532.25,4076.45 1599.31,4076.45 1641.88,4119.03 1641.88,4127.19 1666.9,4152.21 1666.9,4183.99 1706.46,4223.54 1853.5,4223.54 1884.13,4254.17 1941.9,4254.17 1956.87,4269.15 2018.56,4269.15 2052.06,4235.65 2111.31,4235.65 2127.31,4219.65 v3(2126.31,4219.65)
  Inner Layer 5 w4: v2(2080.31,4027.15) 2080.21,4027.25 2081.97,4029.01 2081.97,4036.33 2071.49,4046.81 2071.49,4057.65 2078.97,4065.13 2091.14,4065.13 2101.56,4075.55 2101.56,4103.71 2098.81,4106.46 2098.81,4108.13 2098.81,4164.87 2126.31,4192.38 v3(2126.31,4219.65)
  Bottom w4: v2(2080.31,4027.15) 2080.59,4027.15 C3439.2@2081.65,4026.09 2094.59,4013.15 U3402.6@2108.31,4013.15
BPI_BUS9: C3438.2 U1001.AG22 U3402.5 | length 1775.9
  Top w4: v1(1672.21,4274.44) 1672.24,4274.22 1673.26,4274.31 1680.31,4274.09 1750.31,4274.09 1754.31,4278.09 1865.12,4278.09 1868.95,4274.26 v1(1916.78,4274.26)
  Inner Layer 2 w4: v3(1363.31,4004.09) 1363.46,4004.09 1367.58,3999.97 v4(1392.18,3999.98) ; v3(1665.31,4516.62) 1663.31,4516.62 1663.31,4496.96 1658.31,4491.96 1658.31,4287.18 1671.36,4274.13 v1(1672.21,4274.44) ; v1(1916.78,4274.26) 1927.61,4285.09 1950.19,4285.09 1950.25,4285.15 2029.13,4285.15 2029.19,4285.09 2029.6,4285.09 2063.04,4251.65 2127.6,4251.65 2144.6,4234.65 2155.81,4234.65 2170.81,4219.65 v3(2170.81,4220.65)
  Inner Layer 5 w4: v3(1363.31,4004.09) 1367.31,4008.09 1382.49,4008.09 1406.95,4032.55 1406.95,4215.89 1462.31,4271.25 1462.31,4319.44 1563.63,4420.75 1602.16,4420.75 1629.31,4447.91 1629.31,4481.02 1652.76,4504.47 1653.16,4504.47 v3(1665.31,4516.62) ; v2(2083.37,4000.99) 2083.37,4011.12 2092.31,4020.05 2092.31,4041.04 2117.56,4066.29 2117.56,4110.34 2114.81,4113.09 2114.81,4114.76 ; 2114.81,4114.77 2114.81,4158.24 2134.98,4178.41 2140.72,4184.15 2141.31,4184.15 2170.81,4213.65 v3(2170.81,4220.65)
  Bottom w4: v2(2083.37,4000.99) 2083.28,4001.09 C3438.2@2081.65,4001.09 2085.34,3997.4 U3402.5@2108.31,3997.4
BPI_BUS11: C3805.1 TP3801.1 U1001.AH21 U3801.18 | length 1582
  Top w4: TP3801.1@2150.31,4465.09 2150.31,4485.09 2154.31,4489.09 C3805.1@2155.31,4489.09 ; v1(2155.31,4490.09) C3805.1@2155.31,4489.09 ; U3801.18@2159.51,4586.09 U3801.18@2157.55,4586.09 2158.54,4587.09 2160.31,4587.09 2169.45,4577.95 2169.45,4503.22 2155.81,4489.59 C3805.1@2155.31,4489.09
  Inner Layer 2 w3: v4(1407.93,3984.23) 1407.93,3983.44 1416.2,3983.44 ; 1416.22,3983.47 1450.62,3983.47 1462.92,3995.77
  Inner Layer 2 w4: 1462.92,3995.77 1534.24,4067.09 1601.26,4067.09 1649.95,4115.78 1649.95,4123.02 1674.93,4148 1674.93,4180.71 1709.61,4215.38 1857.24,4215.38 1887.99,4246.13 1945.17,4246.13 1960.19,4261.15 2015.24,4261.15 2048.74,4227.65 2098.84,4227.65 2112.31,4214.18 2112.31,4210.65 2120.81,4202.15 2173.81,4202.15 2201.25,4229.59 2223.24,4229.59 2223.52,4229.31 2251.78,4229.31 v3(2273.41,4207.69) ; v1(2155.31,4490.09) 2158.42,4493.19 v3(2241.4,4493.19)
  Inner Layer 4 w4: v3(2241.4,4493.19) 2277.95,4456.64 2277.95,4215.99 2273.41,4211.45 v3(2273.41,4207.69)
BPI_BUS14: C3806.1 TP3802.1 U1001.AF21 U3801.19 | length 1532.3
  Top w4: C3806.1@2147.31,4664.09 C3806.1@2147.31,4665.09 ; TP3802.1@2147.31,4687.09 v1(2147.31,4666.09) C3806.1@2147.31,4665.09 ; U3801.19@2157.55,4601.84 2165.46,4601.83 2172.31,4608.68 2172.31,4648.87 2156.1,4665.09 C3806.1@2147.31,4665.09
  Inner Layer 2 w4: v3(1355.31,3982.09) 1355.31,3983.16 1376.43,3983.16 v4(1376.43,3984.23) ; v3(1919.31,4656.09) 1949.31,4686.09 1949.31,4710.97 1969.31,4730.97 1969.31,4747.06 1998.34,4776.09 2067.94,4776.09 2147.31,4696.72 v1(2147.31,4666.09)
  Inner Layer 4 w4: v3(1355.31,3982.09) 1366.53,3982.09 1508.57,4124.14 1508.57,4259.11 1508.95,4259.49 1508.95,4275.09 1593.43,4359.57 1593.43,4506.31 1674.01,4586.88 1674.01,4591.2 1693.31,4610.51 1693.31,4630.07 1712.33,4649.09 1912.31,4649.09 v3(1919.31,4656.09)
BPI_BUS15: C3903.1 PA3901.5 TP3901.1 U1001.AG20 | length 760
  Inner Layer 2 w3: v4(1392.18,3968.48) 1395.61,3971.91 1410.53,3971.91 1415.73,3977.11 1455.57,3977.11 1467.15,3988.69
  Inner Layer 2 w4: 1467.15,3988.69 1537.55,4059.09 1604.57,4059.09 1657.95,4112.47 1657.95,4118.97 1682.95,4143.97 1682.95,4177.41 1712.76,4207.22 1860.98,4207.22 1874.07,4220.3 v3(1885.61,4220.3)
  Inner Layer 5 w4: v2(1823.94,4227.84) 1863.61,4227.84 1871.15,4220.3 v3(1885.61,4220.3) 1885.61,4239.61 1892.08,4246.09 v2(1892.08,4259.11)
  Bottom w4: v2(1823.94,4227.84) TP3901.1@1823.95,4227.99 ; v2(1892.08,4259.11) C3903.1@1892.08,4260.11 1892.08,4285.89 PA3901.5@1896.07,4289.88
BPI_BUS18: R3907.1 TP3902.1 U1001.AK21 | length 2920.5
  Top w4: U1001.AK21@1439.43,3984.23 1451.28,3996.09 1460.37,3996.09 1466.37,4002.09 1497.34,4002.09 1578.31,4083.06 v1(1578.31,4124.48) ; R3907.1@1873.95,2874.96 1888.8,2889.81 1937.75,2889.81 1939.5,2891.56 1957.31,2891.56 TP3902.1@1969.31,2879.56 1969.31,2889.24 1975.18,2895.11 1975.31,2894.98 v1(1975.64,2894.83)
  Inner Layer 2 w4: v1(1578.31,4124.48) 1590.77,4124.48 1602.97,4136.68 1602.97,4163.86 1641.49,4202.38 1642.06,4202.38 1693.67,4253.98 1825.17,4253.98 1832.63,4261.44 1832.63,4263.04 1862.68,4293.09 1946.87,4293.09 1946.93,4293.15 2032.44,4293.15 2032.5,4293.09 2034.34,4293.09 2067.39,4260.04 2069.53,4260.04 ; v1(1975.64,2894.83) 1975.35,2895.03 1975.85,2895.78 1981.35,2901.86 2003.95,2901.86 2025.34,2923.25 2025.34,2927.48 2109.7,3011.84 v3(2131.98,3011.84) ; 2069.57,4260.08 2088.62,4260.08 ; 2088.65,4260.04 2130.78,4260.04 2147.74,4243.09 2259.26,4243.09 2307.31,4195.04 2307.31,4143.8 2473.86,3977.25 2473.86,3593.12 2450.28,3569.54 2450.28,3139.06 v3(2424.31,3113.09)
  Inner Layer 4 w4: v3(2131.98,3011.84) 2135.3,3011.09 2174.3,3050.09 2354.3,3050.09 2420.81,3116.59 v3(2424.31,3113.09)
BPI_BUS19: C3902.1 PA3901.4 TP3903.1 U1001.AH19 | length 814.4
  Inner Layer 2 w3: v4(1407.93,3952.73) 1408.79,3952.73 1420.66,3964.6 1460.09,3964.6
  Inner Layer 2 w4: v4@1407.23,3953.43 v4(1407.93,3952.73) ; 1460.09,3964.6 1466.55,3964.6 1532.54,4030.59 1587.38,4030.59 1665.95,4109.15 1665.95,4115.63 1690.95,4140.63 1690.95,4174.1 1716,4199.15 1885.67,4199.15 1905.31,4218.8 v3(1905.31,4231.09)
  Inner Layer 5 w4: v2(1824.15,4209.7) 1855.7,4209.7 1860.1,4205.3 1891.82,4205.3 1897.06,4210.54 1905.31,4218.8 v3(1905.31,4231.09) 1905.31,4251.34 v2(1914.08,4260.11)
  Bottom w4: TP3903.1@1823.95,4207.99 1823.95,4209.5 v2(1824.15,4209.7) ; v2(1914.08,4260.11) C3902.1@1913.08,4260.11 1913.08,4281.5 1920.58,4289 1919.69,4289 PA3901.4@1919.69,4289.88
BPI_BUS20: C3901.1 PA3901.3 TP3904.1 U1001.AK20 | length 821.2
  Top w3: U1001.AK20@1439.43,3968.48 1448.84,3959.06 1459.27,3959.06 1466.3,3966.09 1475.31,3966.09
  Top w4: 1475.31,3966.09 1541.06,3966.09 1546.46,3971.49 v1(1547.95,3971.49)
  Inner Layer 2 w4: v1(1547.95,3971.49) 1548.65,3970.79 1573.23,3970.79 1616.75,4014.32 1616.75,4048.64 1626.84,4058.73 1674.95,4106.84 1674.95,4113.26 1698.95,4137.26 1698.95,4170.78 1719.26,4191.09 1898.82,4191.09 v3(1912.06,4204.33)
  Inner Layer 5 w4: v2(1823.95,4190.49) 1832.05,4198.59 1855.03,4198.59 1857.06,4196.56 1904.29,4196.56 v3(1912.06,4204.33) 1920.31,4212.58 1920.31,4248.06 v2(1931.39,4259.13)
  Bottom w4: PA3901.3@1943.31,4289.88 1943.31,4289 1944.2,4289 1934.08,4278.88 C3901.1@1934.08,4260.11 ; C3901.1@1934.08,4260.11 v2(1931.39,4259.13) 1933.08,4260.11 C3901.1@1934.08,4260.11
C2K_26M_IN: TP3709.1 U1001.AE13 U3701.K3 | length 933.2
  Top w4: U1001.AE13@1360.68,3858.7 v4(1360.69,3858.25) U1001.AE13@1360.22,3858.7 ; v1(1775.69,4547.05) 1780.28,4542.46 U3701.K3@1800.45,4542.46 ; U1001.AE13@1360.22,3858.7 1359.84,3859.09 1360.3,3859.09 1360.47,3858.7 v4(1360.69,3858.25) U1001.AE13@1360.22,3858.7
  Inner Layer 2 w4: v3(1356.95,3883.49) 1356.95,3861.97 v4(1360.69,3858.25) ; v3(1758.31,4549.09) 1773.65,4549.09 v1(1775.69,4547.05)
  Inner Layer 4 w4: v3(1356.95,3883.49) 1401.31,3927.85 1401.31,3994.23 1524.67,4117.58 1524.67,4231.84 1651.98,4359.15 1651.98,4442.76 v3(1758.31,4549.09)
  Inner Layer 5 w4: v3(1758.31,4549.09) 1758.31,4563.09 v2(1758.3,4575.09)
C2K_ANTENNA: C3602.2 CON3802.2 R3604.1 | length 85.1
  Bottom w5: R3604.1@2155.3,4535.09 2156.31,4534.08 2156.31,4519.19 2155.95,4518.83 C3602.2@2155.95,4502.83 2155.95,4460.5 CON3802.2@2162.95,4453.5
C2K_TXBPI: TP3708.1 U1001.AG19 U3701.J10 | length 814.3
  Top w4: v1(1561.31,4047.09) 1590.31,4076.09 1590.31,4129.45 1589.12,4130.64 1589.12,4138.64 v1(1587.96,4138.64) ; TP3708.1@1767.31,4367.09 v1(1785.31,4367.09) 1785.31,4388.09 1791.31,4394.09 1791.31,4407.34 U3701.J10@1816.19,4432.22
  Inner Layer 2 w3: v4(1392.18,3952.73) 1403.53,3964.09 1411.26,3964.09 1418.28,3971.11 1461.07,3971.11 1480.56,3990.59
  Inner Layer 2 w4: 1480.56,3990.59 1537.05,4047.09 v1(1561.31,4047.09) ; v1(1587.96,4138.64) 1594.82,4145.51 1594.82,4167.02 1657.52,4229.72 1657.77,4229.72 1690.16,4262.11 1788.87,4262.11 1825.31,4298.56 1825.31,4317.62 1811.85,4331.09 1805.71,4331.09 1788.81,4347.99 1788.81,4354.58 1785.31,4358.08 v1(1785.31,4367.09)
C2K_VIO18_RF: C3706.1 C3707.1 R3715.2 R3716.2 R3717.2 U3701.K4 | length 404.3
  Top w4: R3717.2@1717.95,4516.49 v1(1717.95,4518.49) ; v1(1737.31,4709.09) 1738.31,4710.09 R3715.2@1738.58,4710.09 ; R3715.2@1737.47,4708.98 R3715.2@1738.58,4710.09 ; v1(1738.52,4644.21) 1738.52,4640.09 C3706.1@1739.31,4640.09 ; R3715.2@1739.31,4710.09 R3715.2@1738.58,4710.09 ; v1(1758.82,4495.23) 1758.95,4495.1 C3707.1@1758.95,4494.49
  Top w8: v1(1758.82,4495.23) 1759.95,4495.23 1767.31,4502.59 1767.31,4502.85 1791.17,4526.71 U3701.K4@1800.45,4526.71
  Top w12: R3716.2@1716.95,4537.49 1716.95,4516.49 R3717.2@1717.95,4516.49
  Inner Layer 2 w4: 1712.99,4568.45 1714.31,4567.13
  Inner Layer 2 w12: v1(1737.31,4709.09) 1714.31,4709.09 1703.44,4698.22 1703.44,4643.09 ; v1(1738.52,4644.21) 1736.65,4646.09 1706.44,4646.09 1703.44,4643.09 ; v1(1758.82,4495.23) 1737.59,4495.23 1717.95,4514.86 v1(1717.95,4518.49) 1714.31,4522.13 1714.31,4567.13 1714.31,4597.93 1703.31,4608.93 1703.31,4642.96 1703.44,4643.09
C2K_VRF18_RF: C3702.1 C3703.1 C3709.1 C3710.1 R3713.2 U3701.A1 U3701.B10 U3701.H10 U3701.K5 | length 1090.2
  Top w4: v1(1807.31,4386.09) 1810.31,4386.09 C3702.1@1810.31,4385.09 ; C3710.1@1941.17,4603.13 v1(1941.3,4603.09) v1(1941.3,4603.09) C3710.1@1941.3,4603 ; v1(1952.31,4352.09) 1954.3,4352.09 R3713.2@1954.3,4353.09
  Top w8: C3703.1@1758.95,4472.32 C3703.1@1760.12,4472.32 ; C3703.1@1758.95,4473.49 1768.95,4473.49 1773.8,4478.33 1773.8,4490.8 1793.95,4510.96 U3701.K5@1800.45,4510.96 ; U3701.B10@1926.43,4432.22 1926.43,4427.14 1936.48,4417.09 1945.11,4417.09 1955.31,4406.89 1955.31,4385.09 C3709.1@1954.31,4384.09 ; C3710.1@1941.17,4603.13 v1(1941.3,4603.09) 1941.3,4603 1942.3,4602 1942.3,4587.42 1942.18,4587.3 U3701.A1@1942.18,4573.96
  Top w10: C3702.1@1810.31,4386.09 1810.31,4400.46 1831.94,4422.09 U3701.H10@1831.94,4432.22
  Top w12: v1(1717.31,4456.09) 1747.69,4456.09 1758.95,4467.34 1758.95,4472.32 C3703.1@1758.95,4473.49 ; R3713.2@1954.3,4353.09 C3709.1@1954.31,4384.09
  Inner Layer 2 w12: v3(1690.06,4586.04) 1697.31,4578.78 1697.31,4470.6 1714.57,4453.34 v1(1717.31,4456.09) 1734.31,4439.09 1734.31,4403.09 1752.31,4385.09 1793.31,4385.09 ; 1793.33,4385.11 v1@1805.31,4385.11 ; v1(1807.31,4386.09) 1807.31,4385.11 v1@1805.31,4385.11 ; v3(1900.31,4575.09) 1915.85,4577.64 v1(1941.3,4603.09) ; v1(1952.31,4352.09) 1952.31,4347.22 1918.18,4313.09 1847.13,4313.09 1817.13,4343.09 1810.69,4343.09 1801.31,4352.46 1801.31,4370.92 1805.31,4374.92 v1@1805.31,4385.11
  Inner Layer 4 w12: v3(1690.06,4586.04) 1700.11,4596.09 1879.31,4596.09 v3(1900.31,4575.09)
C2K_VTCXO2: C3704.1 C3705.1 C3802.1 R3629.2 R3630.2 R3709.2 R3712.2 R3714.2 U3602.4 U3602.5 U3604.4 U3701.D9 U3701.K2 U3801.16 | length 1664
  Top w4: R3714.2@1739.46,4609.53 1738.5,4610.49 R3714.2@1738.38,4610.49 ; v1(1922.31,4389.09) 1922.31,4385.09 C3704.1@1923.3,4385.09 ; v1(2278.31,4523.09) R3709.2@2279.31,4524.09 ; v1(1736.95,4609.49) R3714.2@1737.95,4610.18 ; v1(1736.95,4609.49) R3714.2@1737.95,4610.49 R3714.2@1738.38,4610.49 ; v1(1736.95,4609.49) R3714.2@1737.95,4610.18 ; v1(1736.95,4609.49) R3714.2@1737.95,4610.18 ; R3714.2@1738.1,4610.28 1737.98,4610.2 R3714.2@1738.1,4610.28 ; R3714.2@1738.1,4610.28 R3714.2@1738.18,4610.34 ; R3714.2@1738.1,4610.28 R3714.2@1738.18,4610.34 ; R3714.2@1738.19,4610.34 R3714.2@1738.38,4610.49
  Top w6: R3712.2@1737.95,4557.49 1744.52,4564.06 1744.52,4573.96 C3705.1@1757.05,4586.49 ; R3714.2@1737.95,4609.53 1737.95,4610.18 v1(1736.95,4609.49) ; U3701.K2@1800.01,4557.76 U3701.K2@1800.45,4558.21 1790.23,4558.2 1778.95,4569.49 1778.95,4579.7 1771.17,4587.49 1758.95,4587.49 C3705.1@1758.95,4586.49 ; U3801.16@2157.55,4554.59 2157.55,4515.32 C3802.1@2155.31,4513.09 C3802.1@2158.48,4516.25 ; v1(1736.95,4609.49) R3714.2@1737.95,4609.5 ; v1(1736.95,4609.49) R3714.2@1737.88,4610.25 ; v1(1736.95,4609.49) R3714.2@1737.95,4610.22 ; v1(1736.95,4609.49) R3714.2@1737.95,4609.51 ; v1(1736.95,4609.49) 1737.86,4610.26 1737.77,4610.3 R3714.2@1737.9,4610.3 ; v1(1736.95,4609.49) R3714.2@1737.89,4610.25 ; R3714.2@1737.89,4610.25 R3714.2@1737.95,4610.22 ; R3714.2@1737.89,4610.25 R3714.2@1737.95,4610.3 ; R3714.2@1737.9,4610.3 R3714.2@1737.95,4610.49 ; R3714.2@1737.9,4610.3 R3714.2@1737.95,4610.3 ; R3714.2@1737.9,4610.3 R3714.2@1737.95,4610.49 ; R3714.2@1737.95,4609.49 1746.95,4609.49 1756.95,4599.49 1756.95,4586.49 C3705.1@1757.05,4586.49 ; R3714.2@1737.97,4609.51 R3714.2@1739.46,4609.53 ; R3714.2@1737.95,4610.22 R3714.2@1737.95,4610.3 ; R3714.2@1737.95,4610.3 R3714.2@1737.95,4610.49 ; R3714.2@1737.95,4610.49 1737.95,4610.87 1738.08,4610.76 1738.14,4610.7 R3714.2@1738.38,4610.49 ; R3714.2@1737.95,4610.49 R3714.2@1738.18,4610.35 ; R3714.2@1737.95,4610.49 R3714.2@1737.98,4610.21 ; R3714.2@1737.95,4610.49 1738.18,4610.34 1738.09,4610.29 R3714.2@1737.98,4610.21 ; R3714.2@1737.98,4610.2 R3714.2@1739.46,4609.53 ; R3714.2@1738.18,4610.34 R3714.2@1739.46,4609.53 ; R3714.2@1738.18,4610.35 R3714.2@1738.38,4610.49 ; R3714.2@1738.19,4610.34 R3714.2@1739.46,4609.53 ; R3714.2@1738.38,4610.49 R3714.2@1739.46,4609.53 ; C3705.1@1757.05,4586.49 C3705.1@1757.83,4586.49 ; C3705.1@1757.83,4586.49 C3705.1@1758,4586.49 ; C3705.1@1757.83,4586.49 1757.83,4587.61 C3705.1@1758,4587.44 ; C3705.1@1758,4586.49 C3705.1@1758,4587.44 ; C3705.1@1758,4586.49 C3705.1@1758.95,4586.49 ; C3705.1@1758,4587.44 C3705.1@1758.95,4586.49
  Inner Layer 2 w4: v3(1911.31,4428.09) 1913.09,4427.86 1895.09,4445.87 v4@1897.31,4448.09 ; v4(1894.93,4447.97) v4@1897.31,4448.09 ; v4(1894.93,4447.97) v4@1897.31,4448.09 ; v4(1894.93,4447.97) 1895.05,4448.09 v4@1897.31,4448.09
  Inner Layer 2 w6: v3(1722.31,4623.09) 1722.57,4623.35 1736.69,4609.23 v1(1736.95,4609.49) ; v3(1911.31,4428.09) 1922.31,4417.09 v1(1922.31,4389.09) ; v3(1918.31,4620.09) 1912.31,4623.09 1912.31,4638.09 1903.31,4647.09 1903.31,4663.59 1940.31,4700.59 1940.31,4730.09 v3(1954.31,4744.09) 1953.83,4744.57 1994.34,4785.09 2071.67,4785.09 2159.67,4697.09 v3(2177.3,4697.09) 2177.3,4534.94 v1(2155.33,4512.97) 2268.2,4512.97 v1(2278.31,4523.09)
  Inner Layer 4 w6: v3(1722.31,4623.09) 1728.31,4617.09 1918.31,4617.09 v3(1918.31,4620.09) 1925.31,4613.09 1925.31,4556.68 1912.31,4543.68 1912.31,4480.07 1919.31,4473.07 1919.31,4453.09 1911.31,4445.09 v3(1911.31,4428.09)
  Inner Layer 5 w6: v3(1954.31,4744.09) 1967.3,4731.1 v2(1967.3,4710.09) ; v3(2177.3,4697.09) 2177.48,4697.09 2177.48,4712.16 v2(2177.66,4712.16)
  Bottom w4: R3629.2@1966.3,4711.09 v2(1967.3,4710.09) ; U3602.5@2177.36,4691.02 2177.3,4691.09 2177.36,4694.73 v2(2177.66,4712.16)
  Bottom w6: R3629.2@1966.3,4711.09 R3630.2@1966.3,4677.09 1966.3,4670.09 1966.55,4669.83 U3604.4@2005.43,4669.84 ; 2177.3,4704.09 2177.3,4704.02 2177.36,4704.09 ; U3602.5@2177.37,4688.09 2177.36,4691.02 2177.36,4694.73 2177.36,4704.09 ; U3602.4@2177.37,4713.09 2177.37,4712.16 2177.36,4704.09
CA0: U1001.D6 U4102.Y2 | length 507.5
  Inner Layer 2 w3: v1(611.81,3762.78) 611.81,3733.48 v3(623.89,3721.41)
  Inner Layer 2 w4: v3(1013.88,3743.74) 1025.95,3743.74 1028.95,3746.74 1028.95,3746.99 v4(1029.98,3748.01)
  Inner Layer 4 w3: v3(623.89,3721.41) 626.41,3721.41 641.91,3705.91 648.04,3705.91 685.46,3668.49 930.42,3668.49 1005.67,3743.74 v3(1013.88,3743.74)
CA1: U1001.B6 U4102.Y3 | length 475
  Top w3: v1(925.33,3734.11) 925.33,3740.86 942.21,3757.73 988.75,3757.73 U1001.B6@998.48,3748.01
  Inner Layer 2 w3: v3(627.24,3744.1) 627.24,3758.53 v1(631.5,3762.78) ; v3(920.08,3714.61) 920.38,3715.21 925.33,3720.16 v1(925.33,3734.11)
  Inner Layer 4 w3: v3(627.24,3744.1) 637.56,3733.78 637.56,3720.38 644.97,3712.97 651.54,3712.97 685.02,3679.49 884.96,3679.49 v3(920.08,3714.61)
CA2: U1001.A3 U4102.W2 | length 522.8
  Top w3: v1(969.25,3698.59) 971.43,3700.76 U1001.A3@982.73,3700.77
  Inner Layer 2 w3: v3(596.74,3733.02) 596.74,3767.4 v1(611.81,3782.47) ; v1(969.25,3698.59) v3(984.58,3698.59)
  Inner Layer 4 w3: v3(596.74,3733.02) 610.03,3719.73 610.03,3714.12 619.57,3704.58 633.04,3704.58 638.71,3698.91 645.06,3698.91 684.01,3659.96 945.95,3659.96 v3(984.58,3698.59)
CA3: U1001.A6 U4102.W3 | length 458.3
  Top w3: v1(941.08,3741.61) 949.47,3749.99 980.74,3749.99 U1001.A6@982.73,3748.01
  Inner Layer 2 w3: v1(631.5,3782.47) 632.85,3782.47 v3(649.2,3766.12) ; v1(941.08,3741.61) 942.58,3740.11 v3(942.58,3725.11)
  Inner Layer 4 w3: v3(649.2,3766.12) 667.92,3747.4 667.92,3707.36 688.79,3686.49 871.36,3686.49 915.98,3731.11 936.58,3731.11 v3(942.58,3725.11)
CA4: U1001.A5 U4102.V3 | length 481.9
  Top w3: v1(956.95,3739.49) 975.5,3739.49 U1001.A5@982.73,3732.26
  Inner Layer 2 w3: v1(631.5,3802.15) 634.82,3802.15 v3(648.86,3788.12) ; v1(956.95,3739.49) 956.95,3741.61 971.83,3741.61 v3(971.95,3740.49)
  Inner Layer 4 w3: v3(648.86,3788.12) 677.08,3759.9 677.08,3709.36 690.95,3695.49 867.14,3695.49 914.01,3742.36 971.08,3742.36 971.83,3741.61 v3(971.95,3740.49)
CA5: U1001.D2 U4102.L3 | length 865.1
  Inner Layer 2 w3: v1(631.5,3939.95) 630.34,3941.11 630.34,3950.33 605.07,3975.61 586.84,3975.61 552.58,3941.34 552.58,3688.87 580.84,3660.61 994.33,3660.61 1014.58,3680.86 1018.55,3680.86 1019.3,3681.61 1022.48,3684.78 1029.97,3684.78 v4(1029.98,3685.02)
CA6: U1001.C3 U4102.K3 | length 798
  Top w3: v1(596.08,3959.11) 606.42,3969.45 621.68,3969.45 U4102.K3@631.5,3959.64
  Inner Layer 2 w3: v1(596.08,3959.11) 587.83,3959.11 564.58,3935.86 564.58,3694.36 586.33,3672.61 988.33,3672.61 1014.23,3698.5 v4(1014.23,3700.77)
CA7: U1001.C2 U4102.J3 | length 931.9
  Top w3: U4102.J3@631.5,3979.32 621.66,3989.17 606.7,3989.17 599.26,3996.61 589.48,3996.61 578.14,3985.27 578.14,3975.39 534.58,3931.83 534.58,3681.41 573.45,3642.55 991.18,3642.55 993.64,3640.09 1012.37,3640.09 1019.26,3646.98 1019.26,3653.63 1019.08,3653.81 1019.08,3680.16 U1001.C2@1014.23,3685.02
CA8: U1001.B2 U4102.J2 | length 830.7
  Top w3: U4102.J2@611.82,3979.32 610.87,3980.27 606.05,3975.45 597.95,3975.45 592.11,3969.61 589.33,3969.61 546.58,3926.86 546.58,3686.39 578.36,3654.61 997.14,3654.61 1007.9,3665.37 1007.9,3675.6 U1001.B2@998.48,3685.02
CA9: U1001.D1 U4102.H2 | length 892.8
  Top w3: v1(599.08,4007.11) 603.71,4007.11 U4102.H2@611.82,3999.01
  Top w4: v1(1029.58,3656.11) 1029.78,3656.11 1029.78,3669.27 U1001.D1@1029.98,3669.27
  Inner Layer 2 w3: v1(599.08,4007.11) 592.68,4000.71 589.34,4000.71 572.31,3983.69 572.31,3978.58 540.58,3946.85 540.58,3683.9 576.4,3648.09 992.31,3648.09 1000.31,3640.09 1012.92,3640.09 1028.94,3656.11 v1(1029.58,3656.11)
CAM_PDN0: CON6201.24 U1001.AJ26 | length 1522.9
  Top w4: U1001.AJ26@1423.31,4062.61 v4(1423.68,4062.97) 1423.31,4062.97 U1001.AJ26@1423.31,4062.61
  Inner Layer 2 w4: v3(1349.95,4702.83) 1351.31,4702.83 1351.31,4691.39 1393.61,4649.09 1422.8,4649.09 1532.31,4539.57 1532.31,4493.81 v3(1550.97,4475.15) ; v4(1423.68,4062.97) 1432.32,4071.61 1434.84,4071.61 v3(1446.31,4083.09)
  Inner Layer 4 w4: v3(1446.31,4083.09) 1416.31,4113.09 1416.31,4228.11 1550.97,4362.77 v3(1550.97,4475.15)
  Inner Layer 5 w4: v2(1324.31,4480.09) 1324.31,4494.31 1314.31,4504.31 1314.31,4667.19 v3(1349.95,4702.83)
  Bottom w4: CON6201.24@1046.63,4190.15 1046.63,4189.15 1055.9,4189.15 1066.31,4199.56 1066.31,4303.31 1243.09,4480.09 v2(1324.31,4480.09)
CAM_PDN1: CON6202.24 U1001.AK25 | length 1419.9
  Top w3: U1001.AK25@1439.43,4047.22 1461.3,4047.22 1461.43,4047.09 1485.76,4047.09 1489.7,4051.03
  Top w4: 1489.7,4051.03 1533.31,4094.64 1533.31,4123.09 v1(1529.07,4127.33) ; v1(1711.95,5035.49) 1711.95,5050.05 CON6202.24@1712.31,5050.41 ; CON6202.24@1712.31,5042.09 CON6202.24@1712.31,5050.41 ; CON6202.24@1712.96,5053.06 1711.95,5063.84 1712.96,5063.84 1712.96,5051.05 CON6202.24@1712.31,5050.41
  Inner Layer 2 w4: v1(1529.07,4127.33) 1529.07,4136.32 1634.31,4241.56 1634.31,4592.04 1656.31,4614.04 1656.31,4649.55 1505.6,4800.26 1505.6,4847.4 1489.82,4863.17 1489.82,4985.91 1534.37,5030.46 1706.92,5030.46 v1(1711.95,5035.49)
CAM_RST1: CON6202.22 U1001.AG25 | length 1489
  Inner Layer 2 w3: v4(1392.18,4047.22) 1403.29,4036.11 1441.22,4036.11 1453.22,4048.11 1458.16,4048.11 1479.14,4069.09 1479.14,4081.91 1479.31,4082.09
  Inner Layer 2 w4: 1479.31,4076.22 1479.31,4082.09 1479.31,4110.02 1618.31,4249.02 1618.31,4599.95 1640.31,4621.95 1640.31,4642.38 1443.31,4839.38 1443.31,4973.34 1528.06,5058.09 1687.77,5058.09 1693.92,5064.24 1721.23,5064.24 1725.22,5068.23 v1(1729.26,5068.23)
